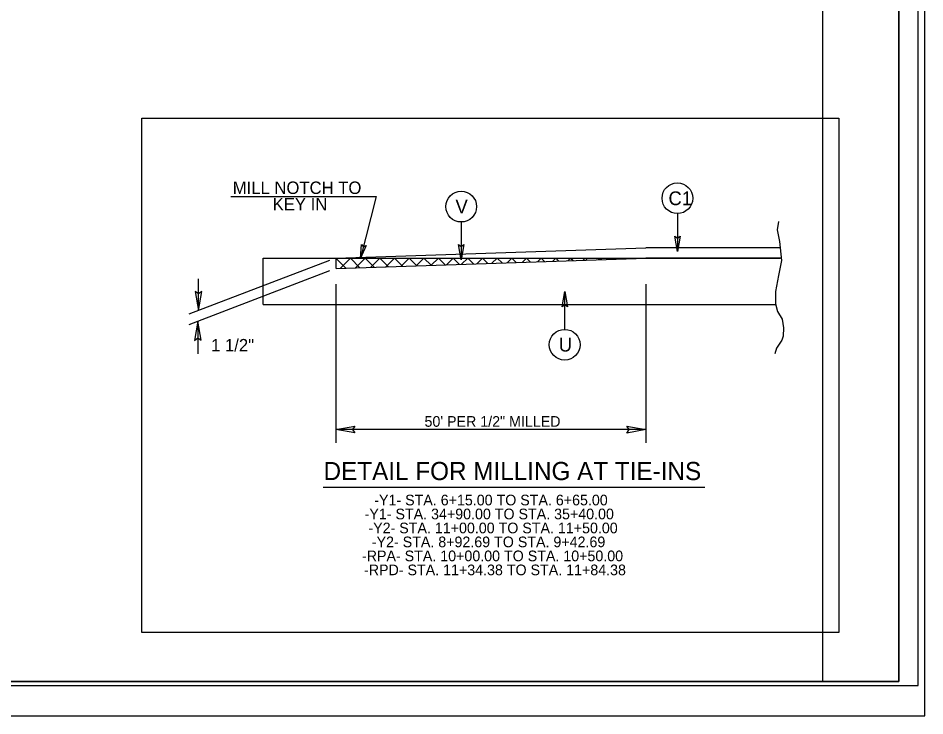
# Model space of a CAD drawing. Extents: x 1640342 to 1730599, y 538663 to 843747.
# Drawn here: x 1730058.2 to 1730177.4, y 539863.4 to 539955 of the extents above; entities that cross this region are included whole.
import ezdxf

# ---------------------------------------------------------------- set-up
doc = ezdxf.new("R2010")
doc.units = 0
for name, color, linetype in [('Old_Level_1', 7, 'Continuous'), ('Old_Level_11', 7, 'Continuous'), ('Sheet Clip Boundary CELL', 7, 'Continuous'), ('Sheet Layout Plan Border', 7, 'Continuous'), ('Sheet Plan CELL', 7, 'Continuous'), ('Sheet Plan Layout CELL', 7, 'Continuous'), ('Sheet Plot Border Inside CELL', 7, 'Continuous'), ('Sheet Plot Border Outside CELL', 7, 'Continuous'), ('Typical Detail Wedge2 CELL', 7, 'Continuous'), ('Typical ID Circle CELL', 7, 'Continuous'), ('Typical Terminator CELL', 7, 'Continuous'), ('Typical Text General CELL', 7, 'Continuous'), ('Typical Text ID Circle CELL', 7, 'Continuous'), ('Typical Text Label CELL', 7, 'Continuous')]:
    doc.layers.add(name, color=color, linetype=linetype)

msp = doc.modelspace()

# ---------------------------------------------------------------- linework, layer by layer
at = {"layer": 'Old_Level_1'}
for p, q in [((1730086.11, 539931.59), (1730105.26, 539931.59)), ((1730105.26, 539931.59), (1730103.19, 539923.49)), ((1730099.92, 539923.51), (1730140.7, 539924.88)), ((1730158.34, 539924.88), (1730140.7, 539924.88)), ((1730090.37, 539923.51), (1730158.38, 539923.51)), ((1730090.37, 539917.43), (1730090.37, 539923.51)), ((1730099.92, 539923.51), (1730099.92, 539922.15)), ((1730099.96, 539922.15), (1730140.75, 539923.51)), ((1730158.49, 539923.51), (1730140.7, 539923.51)), ((1730099.11, 539923.2), (1730080.59, 539916.13)), ((1730099.09, 539921.83), (1730080.59, 539914.76)), ((1730081.89, 539916.62), (1730081.89, 539920.79)), ((1730099.92, 539920.11), (1730099.92, 539899.26)), ((1730140.7, 539920.11), (1730140.7, 539899.26)), ((1730090.37, 539917.43), (1730157.77, 539917.43)), ((1730081.79, 539915.22), (1730081.79, 539910.94)), ((1730140.7, 539900.98), (1730099.92, 539900.98))]:
    msp.add_line(p, q, dxfattribs=at)
at = {"layer": 'Old_Level_11'}
for points in [[(1730103.93, 539925.15), (1730103.19, 539923.49), (1730103.33, 539925.32), (1730103.58, 539925.01)], [(1730081.45, 539919.13), (1730081.89, 539916.62), (1730082.33, 539919.14), (1730081.89, 539918.82)], [(1730082.22, 539912.72), (1730081.79, 539915.22), (1730081.35, 539912.7), (1730081.79, 539913.02)], [(1730102.42, 539900.55), (1730099.92, 539900.98), (1730102.44, 539901.42), (1730102.12, 539900.98)], [(1730138.2, 539901.41), (1730140.7, 539900.98), (1730138.18, 539900.53), (1730138.5, 539900.98)]]:
    msp.add_lwpolyline(points, close=True, dxfattribs=at)
at = {"layer": 'Sheet Clip Boundary CELL'}
msp.add_lwpolyline([(1729883.99, 539867.86), (1730163.99, 539867.86), (1730163.99, 540035.56), (1730126.14, 540035.56), (1730126.14, 540077.86), (1729883.99, 540077.86)], close=True, dxfattribs=at)
at = {"layer": 'Sheet Layout Plan Border'}
msp.add_lwpolyline([(1729883.99, 539867.86), (1730163.99, 539867.86), (1730163.99, 540035.56), (1730126.14, 540035.56), (1730126.14, 540077.86), (1729883.99, 540077.86)], close=True, dxfattribs=at)
at = {"layer": 'Sheet Plan CELL'}
for points in [[(1730174, 540077.86), (1729873.99, 540077.86), (1729873.99, 539867.86), (1730173.99, 539867.86)], [(1729873.99, 539867.86), (1729873.99, 540077.86), (1730133.98, 540077.86), (1730133.99, 540047.85), (1730173.99, 540047.85), (1730173.99, 539867.86)]]:
    msp.add_lwpolyline(points, close=True, dxfattribs=at)
at = {"layer": 'Sheet Plan Layout CELL'}
msp.add_lwpolyline([(1729873.99, 540077.86), (1729873.99, 539867.86), (1730173.99, 539867.86), (1730173.99, 540035.56), (1730126.14, 540035.56), (1730126.14, 540077.86)], close=True, dxfattribs=at)
at = {"layer": 'Sheet Plot Border Inside CELL'}
msp.add_lwpolyline([(1729843.29, 539867.36), (1730176.49, 539867.36), (1730176.49, 540078.36), (1729843.29, 540078.36)], close=True, dxfattribs=at)
at = {"layer": 'Sheet Plot Border Outside CELL'}
msp.add_lwpolyline([(1729840.69, 539863.36), (1730177.39, 539863.36), (1730177.39, 540082.36), (1729840.69, 540082.36)], close=True, dxfattribs=at)
at = {"layer": 'Typical Detail Wedge2 CELL'}
for p, q in [((1730099.92, 539923.51), (1730101.24, 539922.19)), ((1730100.5, 539922.17), (1730101.85, 539923.51)), ((1730101.85, 539923.51), (1730103.11, 539922.25)), ((1730102.5, 539922.23), (1730103.78, 539923.51)), ((1730103.78, 539923.51), (1730104.98, 539922.32)), ((1730104.5, 539922.3), (1730105.71, 539923.51)), ((1730105.71, 539923.51), (1730106.84, 539922.38)), ((1730106.49, 539922.37), (1730107.64, 539923.51)), ((1730107.64, 539923.51), (1730108.71, 539922.44)), ((1730108.49, 539922.43), (1730109.57, 539923.51)), ((1730109.57, 539923.51), (1730110.58, 539922.5)), ((1730110.49, 539922.5), (1730111.5, 539923.51)), ((1730111.5, 539923.51), (1730112.45, 539922.57)), ((1730112.49, 539922.57), (1730113.43, 539923.51)), ((1730113.43, 539923.51), (1730114.31, 539922.63)), ((1730114.48, 539922.63), (1730115.36, 539923.51)), ((1730115.36, 539923.51), (1730116.18, 539922.69)), ((1730116.48, 539922.7), (1730117.29, 539923.51)), ((1730117.29, 539923.51), (1730118.05, 539922.75)), ((1730118.48, 539922.77), (1730119.22, 539923.51)), ((1730119.22, 539923.51), (1730119.92, 539922.82)), ((1730120.47, 539922.84), (1730121.15, 539923.51)), ((1730121.15, 539923.51), (1730121.79, 539922.88)), ((1730122.47, 539922.9), (1730123.08, 539923.51)), ((1730123.08, 539923.51), (1730123.65, 539922.94)), ((1730124.47, 539922.97), (1730125.01, 539923.51)), ((1730125.01, 539923.51), (1730125.52, 539923)), ((1730126.47, 539923.04), (1730126.94, 539923.51)), ((1730126.94, 539923.51), (1730127.39, 539923.07)), ((1730128.46, 539923.1), (1730128.87, 539923.51)), ((1730128.87, 539923.51), (1730129.26, 539923.13)), ((1730130.46, 539923.17), (1730130.8, 539923.51)), ((1730130.8, 539923.51), (1730131.13, 539923.19)), ((1730132.46, 539923.24), (1730132.74, 539923.51)), ((1730132.73, 539923.51), (1730132.99, 539923.25)), ((1730134.46, 539923.3), (1730134.67, 539923.51)), ((1730134.66, 539923.51), (1730134.86, 539923.32)), ((1730136.45, 539923.37), (1730136.6, 539923.51)), ((1730136.59, 539923.51), (1730136.73, 539923.38)), ((1730138.45, 539923.44), (1730138.53, 539923.51)), ((1730138.53, 539923.51), (1730138.6, 539923.44)), ((1730140.45, 539923.5), (1730140.46, 539923.51)), ((1730140.46, 539923.51), (1730140.47, 539923.5))]:
    msp.add_line(p, q, dxfattribs=at)
msp.add_lwpolyline([(1730158.16, 539928.31), (1730157.96, 539927.23), (1730158.26, 539925.69), (1730158.52, 539923.2), (1730158.16, 539921.23), (1730157.73, 539919.11), (1730157.77, 539917.5), (1730158.03, 539916.49), (1730158.62, 539915.47), (1730158.82, 539914.35), (1730158.78, 539913.24), (1730158.59, 539912.72), (1730157.9, 539911.67), (1730157.67, 539910.95)], dxfattribs=at)
at = {"layer": 'Typical ID Circle CELL'}
for p, q in [((1730144.85, 539929.36), (1730144.85, 539924.39)), ((1730116.42, 539928.27), (1730116.42, 539923.29)), ((1730130.03, 539914.15), (1730130.03, 539919.12))]:
    msp.add_line(p, q, dxfattribs=at)
for centre in [(1730144.85, 539931.38), (1730116.42, 539930.28), (1730130.03, 539912.13)]:
    msp.add_circle(centre, 2.02, dxfattribs=at)
at = {"layer": 'Typical Terminator CELL'}
for points in [[(1730145.2, 539926.4), (1730144.85, 539924.39), (1730144.5, 539926.41), (1730144.85, 539926.15)], [(1730116.76, 539925.3), (1730116.42, 539923.29), (1730116.06, 539925.31), (1730116.42, 539925.06)], [(1730129.69, 539917.11), (1730130.03, 539919.12), (1730130.39, 539917.1), (1730130.03, 539917.36)]]:
    msp.add_lwpolyline(points, close=True, dxfattribs=at)
at = {"layer": 'Typical Text General CELL'}
for p, q in [((1730074.43, 539941.91), (1730166.09, 539941.91)), ((1730074.43, 539874.31), (1730074.43, 539941.91)), ((1730166.09, 539941.91), (1730166.09, 539874.31)), ((1730166.09, 539874.31), (1730074.43, 539874.31))]:
    msp.add_line(p, q, dxfattribs=at)
at = {"layer": 'Typical Text Label CELL'}
msp.add_line((1730098.25, 539893.4), (1730148.44, 539893.4), dxfattribs=at)

# ---------------------------------------------------------------- texts
at = {"layer": 'Old_Level_1'}
for s, height, p in [('MILL NOTCH TO ', 1.638, (1730086.38, 539931.94)), ('KEY IN', 1.638, (1730091.63, 539929.79)), ('1 1/2"', 1.638, (1730083.53, 539911.25)), ('50\' PER 1/2" MILLED', 1.4, (1730111.6, 539901.35))]:
    msp.add_text(s, height=height, dxfattribs=at).set_placement(p)
at = {"layer": 'Typical Text General CELL'}
msp.add_text('DETAIL FOR MILLING AT TIE-INS', height=2.3871, dxfattribs=at).set_placement((1730098.32, 539894.34))
at = {"layer": 'Typical Text ID Circle CELL'}
for s, height, p in [('C1', 1.808, (1730143.68, 539930.47)), ('V', 1.81, (1730115.67, 539929.38)), ('U', 1.81, (1730129.25, 539911.23))]:
    msp.add_text(s, height=height, rotation=360, dxfattribs=at).set_placement(p)
at = {"layer": 'Typical Text Label CELL'}
for s, p in [('-Y1- STA. 6+15.00 TO STA. 6+65.00', (1730104.99, 539891.02)), ('-Y1- STA. 34+90.00 TO STA. 35+40.00', (1730103.72, 539889.19)), ('-Y2- STA. 11+00.00 TO STA. 11+50.00', (1730104.22, 539887.35)), ('-Y2- STA. 8+92.69 TO STA. 9+42.69', (1730104.67, 539885.52)), ('-RPA- STA. 10+00.00 TO STA. 10+50.00', (1730103.37, 539883.68)), ('-RPD- STA. 11+34.38 TO STA. 11+84.38', (1730103.64, 539881.84))]:
    msp.add_text(s, height=1.4, dxfattribs=at).set_placement(p)

doc.saveas('drawing.dxf')
